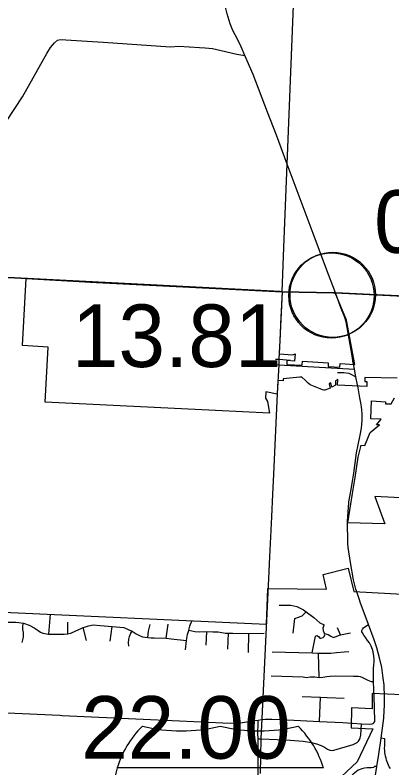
# Model space of a CAD drawing. Extents: x 1729596 to 1934326, y 644115 to 911751.
# Drawn here: x 1812555 to 1819179, y 770599 to 783844 of the extents above; entities that cross this region are included whole.
import ezdxf

# ---------------------------------------------------------------- set-up
doc = ezdxf.new("R2010")
doc.units = 0
for name, color, linetype in [('Default', 7, 'Continuous'), ('GM_X_City_Street', 7, 'Continuous'), ('GM_X_Corporation', 7, 'Continuous'), ('GM_X_County', 7, 'Continuous'), ('GM_X_County_Road', 7, 'Continuous'), ('GM_X_Interchange_Ramps', 7, 'Continuous'), ('GM_X_Interstate_Shield', 7, 'Continuous'), ('GM_X_State_Route', 7, 'Continuous'), ('GM_X_Township', 7, 'Continuous'), ('GM_X_Township_Road', 7, 'Continuous')]:
    doc.layers.add(name, color=color, linetype=linetype)

msp = doc.modelspace()

# ---------------------------------------------------------------- linework, layer by layer
at = {"layer": 'Default'}
for centre in [(1818116, 778911), (1818116, 778911), (1818138, 778922)]:
    msp.add_circle(centre, 750, dxfattribs=at)
at = {"layer": 'GM_X_City_Street'}
for points in [[(1817132, 777792), (1817193, 777788), (1817395, 777775)], [(1817061, 777694), (1817188, 777688), (1818521, 777615)], [(1818222, 777553), (1818332, 777555), (1818419, 777545), (1818458, 777529), (1818546, 777480)], [(1817196, 773460), (1817403, 773460), (1817510, 773437), (1817625, 773383), (1817674, 773345), (1817809, 773245), (1817909, 773153), (1817986, 773119)], [(1813151, 772955), (1813176, 773303)], [(1817470, 773228), (1817601, 773272), (1817674, 773345)], [(1812285, 772887), (1812322, 773009), (1812344, 773096), (1812384, 773138), (1812438, 773164), (1812566, 773165), (1812622, 773156)], [(1812622, 773156), (1812623, 773156), (1812696, 773145), (1812701, 773144), (1812804, 773108), (1812900, 773056), (1812999, 772990), (1813043, 772971), (1813143, 772955), (1813151, 772955), (1813419, 772950), (1813477, 772956), (1813480, 772957), (1813535, 772971), (1813625, 773011), (1813716, 773054), (1813754, 773067), (1813790, 773080), (1813848, 773096), (1813926, 773115), (1814050, 773105), (1814263, 773086), (1814466, 773067), (1814545, 773036), (1814615, 773004), (1814681, 772956), (1814743, 772928), (1814795, 772903), (1814889, 772892), (1814945, 772889), (1814997, 772889), (1815212, 772882), (1815301, 772871), (1815569, 772838)], [(1812678, 772805), (1812702, 772900), (1812705, 772935), (1812703, 772984), (1812693, 773034), (1812689, 773072), (1812691, 773101), (1812701, 773144)], [(1813480, 772957), (1813480, 773165)], [(1814889, 772892), (1814903, 773007), (1814929, 773121)], [(1815212, 772882), (1815246, 773127)], [(1815548, 772678), (1815569, 772838), (1815585, 772948), (1815609, 773015), (1815610, 773021), (1815628, 773095), (1815642, 773143), (1815667, 773188)], [(1817445, 772968), (1817470, 773228)], [(1817774, 772623), (1817833, 772919), (1817856, 772931), (1817889, 772912), (1817909, 772882), (1817927, 772882), (1817968, 772894), (1817986, 772909), (1817998, 772943), (1817995, 772959), (1817993, 772965), (1817974, 773013), (1817971, 773062), (1817986, 773119)], [(1818873, 771627), (1818871, 771678), (1818854, 772118), (1818852, 772295), (1818853, 772356), (1818861, 772408), (1818867, 772467), (1818866, 772514), (1818863, 772566), (1818850, 772642), (1818835, 772684), (1818811, 772743), (1818783, 772799), (1818751, 772841), (1818719, 772889), (1818683, 772936), (1818661, 772973), (1818652, 772995), (1818652, 773017), (1818659, 773039), (1818677, 773064), (1818702, 773082), (1818765, 773124)], [(1813811, 772842), (1813754, 773067)], [(1814229, 772832), (1814263, 773086)], [(1814552, 772741), (1814551, 772801), (1814555, 772862), (1814567, 772910), (1814579, 772942), (1814587, 772968), (1814615, 773004)], [(1815610, 773021), (1815713, 772999), (1815789, 772993), (1815923, 772998), (1816029, 772995), (1816123, 772993), (1816255, 772970), (1816304, 772970), (1816381, 772968), (1816664, 772964), (1816933, 772969)], [(1815913, 772757), (1815923, 772998)], [(1818277, 772940), (1818222, 773066)], [(1816293, 772687), (1816304, 772970)], [(1816657, 772632), (1816664, 772964)], [(1817993, 772965), (1818057, 772946), (1818103, 772919), (1818149, 772891), (1818259, 772937), (1818277, 772940), (1818452, 772974)], [(1817073, 772643), (1817774, 772623), (1817890, 772620), (1818006, 772620), (1818106, 772620), (1818204, 772628), (1818338, 772640), (1818422, 772649)], [(1817898, 772188), (1817890, 772620)], [(1817054, 772221), (1817621, 772200), (1817677, 772192), (1817743, 772199), (1817821, 772199), (1817898, 772188), (1817963, 772197), (1818037, 772207), (1818093, 772211), (1818192, 772218), (1818502, 772214), (1818586, 772212), (1818618, 772207), (1818649, 772198), (1818685, 772180), (1818720, 772161), (1818754, 772142), (1818782, 772129), (1818814, 772122), (1818835, 772121), (1818854, 772118)], [(1817601, 771858), (1817925, 771844), (1818043, 771840)], [(1817904, 771414), (1817925, 771844)], [(1818043, 771840), (1818337, 771828)], [(1810166, 771668), (1811067, 771629), (1811881, 771593), (1813341, 771526)], [(1813341, 771526), (1813385, 771524), (1814809, 771455), (1816335, 771388), (1816520, 771395), (1816625, 771410), (1816741, 771431), (1816828, 771442)], [(1816760, 769259), (1816764, 769392), (1816764, 769469), (1816790, 769800), (1816815, 770182), (1816827, 770503), (1816828, 771008), (1816826, 771113), (1816822, 771208), (1816828, 771372), (1816828, 771442)], [(1816828, 771442), (1816890, 771453), (1816953, 771456), (1817066, 771455), (1817222, 771449), (1817569, 771434), (1817904, 771414), (1818313, 771397), (1818479, 771385), (1818485, 771385)], [(1816826, 771113), (1816873, 771111), (1817162, 771100), (1817389, 771086), (1817617, 771069), (1817764, 771048), (1817853, 771022), (1817935, 770992), (1817996, 770965), (1818049, 770930), (1818088, 770911), (1818130, 770906), (1818156, 770909), (1818497, 771014), (1818569, 771047), (1818594, 771069), (1818611, 771098), (1818623, 771126), (1818630, 771176), (1818645, 771375)]]:
    msp.add_lwpolyline(points, dxfattribs=at)
at = {"layer": 'GM_X_Corporation'}
for points in [[(1819268, 777456), (1818703, 777466), (1818702, 777396), (1818737, 777395), (1818738, 777311), (1818223, 777335), (1818227, 777430), (1818185, 777409), (1818187, 777330), (1818125, 777299), (1818105, 777371), (1818074, 777354), (1818094, 777281), (1818047, 777262), (1818016, 777249), (1817997, 777245), (1817979, 777246), (1817957, 777251), (1817918, 777268), (1817743, 777338), (1817706, 777368), (1817659, 777415), (1817598, 777471), (1817589, 777474), (1817558, 777471), (1817270, 777444), (1817267, 777407), (1817175, 777415), (1817162, 777174), (1816963, 777214), (1816955, 777103), (1816990, 777043), (1817028, 776838), (1816077, 776890), (1813084, 777036), (1813135, 778003), (1812688, 778029), (1812748, 779209), (1813989, 779140), (1817250, 778977), (1817198, 777883), (1817437, 777868), (1817477, 777883), (1817466, 777757), (1817333, 777768), (1817329, 777699), (1817602, 777686), (1817606, 777753), (1818060, 777725), (1818058, 777659), (1818265, 777648), (1818267, 777712), (1818526, 777699), (1818382, 778477), (1818182, 778957), (1823932, 778674)], [(1822492, 775187), (1818880, 775374), (1819053, 774896), (1818404, 774908), (1818486, 775425), (1818535, 775710), (1818583, 776065), (1818636, 776280), (1818700, 776269), (1818798, 776499), (1818958, 776635), (1818908, 776636), (1818992, 776737), (1818809, 776740), (1818820, 777055), (1819068, 777042), (1819068, 777007), (1819165, 777003), (1819223, 777108)], [(1812090, 773353), (1816972, 773128), (1816996, 773757), (1818030, 773743), (1817968, 774000), (1818411, 774114), (1818508, 773703), (1819478, 773652)], [(1819885, 771859), (1818834, 771906), (1818829, 771638), (1818467, 771654), (1818460, 771305), (1818845, 771288), (1818565, 770709), (1818102, 770270)]]:
    msp.add_lwpolyline(points, dxfattribs=at)
at = {"layer": 'GM_X_County'}
for points in [[(1811853, 779256), (1817214, 778979), (1817250, 778977), (1818151, 778958), (1818187, 778957), (1823936, 778682), (1823966, 778677), (1824141, 778666), (1825025, 778622), (1825481, 778599), (1825506, 778597), (1825736, 778586), (1825825, 778586), (1826422, 778555), (1827092, 778520), (1827440, 778500), (1827947, 778461)], [(1827947, 778461), (1827440, 778500), (1827092, 778520), (1826422, 778555), (1825825, 778586), (1825736, 778586), (1825506, 778597), (1825481, 778599), (1825025, 778622), (1824141, 778666), (1823966, 778677), (1823936, 778682), (1818187, 778957), (1818151, 778958), (1817250, 778977), (1817214, 778979), (1811853, 779256)]]:
    msp.add_lwpolyline(points, dxfattribs=at)
at = {"layer": 'GM_X_County_Road'}
for points in [[(1818846, 771380), (1818847, 771380), (1818861, 771391), (1818876, 771413), (1818879, 771447), (1818873, 771627)], [(1818485, 771385), (1818645, 771375), (1818790, 771369), (1818829, 771373), (1818846, 771380)]]:
    msp.add_lwpolyline(points, dxfattribs=at)
at = {"layer": 'GM_X_Interchange_Ramps'}
for points in [[(1819151, 770587), (1819133, 770618), (1819119, 770646), (1819106, 770677), (1819095, 770704), (1819084, 770735), (1819075, 770768), (1819066, 770804), (1819059, 770842), (1819055, 770872), (1819052, 770905), (1819051, 770939), (1819052, 770986), (1819053, 771107), (1819053, 771111), (1818989, 771120)], [(1818911, 770622), (1818874, 770625), (1818854, 770609), (1818821, 770601), (1818743, 770598), (1818696, 770594), (1818647, 770583), (1818588, 770560), (1818524, 770512), (1818498, 770490), (1818096, 770130), (1817974, 770033), (1817872, 769964), (1817768, 769899), (1817684, 769854), (1817639, 769841), (1817557, 769828), (1817557, 769791)]]:
    msp.add_lwpolyline(points, dxfattribs=at)
at = {"layer": 'GM_X_Interstate_Shield'}
msp.add_line((1817975, 770599), (1814349, 770599), dxfattribs=at)
msp.add_line((1817975, 770599), (1814349, 770599), dxfattribs=at)
for centre, start_param, end_param in [((1816631, 770170), 2.47259, 2.911027), ((1815477, 773126), 4.415841, 5.008937), ((1816847, 773126), 4.415841, 5.008937), ((1815693, 770170), 0.230566, 0.669003), ((1816631, 770170), 2.911027, 4.511031)]:
    msp.add_ellipse(centre, major_axis=(2344, 0), ratio=0.8, start_param=start_param, end_param=end_param, dxfattribs=at)
at = {"layer": 'GM_X_State_Route'}
for points in [[(1818019, 779405), (1817795, 780002), (1817338, 781221), (1817148, 781730), (1816994, 782133), (1816739, 782797), (1816596, 783133), (1816530, 783286), (1816466, 783417), (1816381, 783573), (1816336, 783687), (1816285, 783865), (1816160, 784364), (1816076, 784730), (1816020, 785073), (1815987, 785293), (1815970, 785528), (1815949, 786077)], [(1818187, 778957), (1818019, 779405)], [(1818503, 777708), (1818500, 777720), (1818479, 777849), (1818393, 778345), (1818373, 778448), (1818352, 778526), (1818275, 778711), (1818187, 778957)], [(1818574, 777338), (1818546, 777480), (1818521, 777615), (1818503, 777708)], [(1818423, 775269), (1818423, 775279), (1818460, 775498), (1818491, 775679), (1818508, 775782), (1818558, 776141), (1818586, 776285), (1818622, 776453), (1818642, 776575), (1818654, 776709), (1818654, 776832), (1818646, 776949), (1818635, 777020), (1818617, 777108), (1818585, 777285), (1818574, 777338)], [(1818554, 773715), (1818545, 773742), (1818504, 773909), (1818450, 774214), (1818411, 774477), (1818401, 774556), (1818396, 774933), (1818423, 775269)], [(1818621, 773517), (1818606, 773559), (1818554, 773715)], [(1818765, 773124), (1818621, 773517)], [(1819044, 772009), (1819042, 772062), (1819026, 772181), (1819002, 772364), (1818961, 772537), (1818913, 772710), (1818865, 772850), (1818765, 773124)], [(1819035, 771484), (1819051, 771710), (1819050, 771894), (1819044, 772009)], [(1818946, 770843), (1818989, 771120), (1819034, 771474), (1819035, 771484)], [(1818800, 769779), (1818844, 770110), (1818891, 770469), (1818911, 770622), (1818946, 770843)]]:
    msp.add_lwpolyline(points, dxfattribs=at)
at = {"layer": 'GM_X_Township'}
for points in [[(1817250, 778977), (1817281, 779754), (1817338, 781221), (1817524, 785929), (1817856, 792932), (1818194, 800042), (1818544, 806864)], [(1817214, 778979), (1817250, 778977), (1817223, 778414), (1817214, 778229), (1817193, 777788), (1817188, 777688), (1817164, 777187), (1817096, 775760), (1817079, 775415), (1817060, 775014), (1817044, 774665), (1817027, 774315), (1817008, 773931), (1816890, 771467), (1816873, 771111), (1816864, 770504)], [(1817250, 778977), (1817214, 778979)]]:
    msp.add_lwpolyline(points, dxfattribs=at)
at = {"layer": 'GM_X_Township_Road'}
msp.add_lwpolyline([(1812415, 781994), (1812688, 782408), (1813116, 783166), (1813176, 783276), (1813250, 783357), (1813300, 783402), (1813355, 783411), (1814105, 783369), (1815284, 783286), (1815431, 783297), (1815798, 783276), (1815898, 783270), (1816026, 783253), (1816177, 783222), (1816452, 783156), (1816596, 783133)], dxfattribs=at)

# ---------------------------------------------------------------- texts
at = {"layer": 'Default'}
for s, p in [('0.00', (1818866, 779661)), ('13.81', (1813554, 777652)), ('22.00', (1813717, 770762))]:
    msp.add_text(s, height=1100, dxfattribs=at).set_placement(p)

doc.saveas('drawing.dxf')
